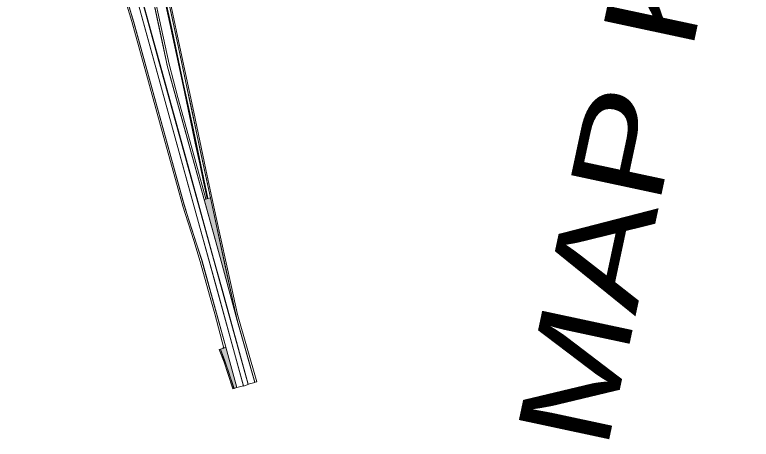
# Model space of a CAD drawing. Extents: x 2363411 to 2369702, y 6977197 to 6988655.
# Drawn here: x 2367822.8 to 2367997.2, y 6986995.7 to 6987096.2 of the extents above; entities that cross this region are included whole.
import ezdxf

# ---------------------------------------------------------------- set-up
doc = ezdxf.new("R2010")
doc.units = 0
doc.header["$LTSCALE"] = 5.6
for name, color, linetype, lineweight in [('10', 7, 'Continuous', 13), ('11', 7, 'Continuous', 13), ('62', 7, 'Continuous', 25)]:
    doc.layers.add(name, color=color, linetype=linetype, lineweight=lineweight)

msp = doc.modelspace()

# ---------------------------------------------------------------- hatches: boundary and pattern name
at = {"layer": '10'}
msp.add_hatch(color=256, dxfattribs=at).paths.add_polyline_path([(2367874.494, 6987007.693), (2367873.305, 6987011.337), (2367872.422, 6987014), (2367871.271, 6987016.959), (2367871.527, 6987017.052), (2367872.505, 6987014.536), (2367873.304, 6987012.164), (2367874.771, 6987007.765)])
at = {"layer": '11'}
for points in [[(2367869.165, 6987052.873), (2367867.69, 6987052.468), (2367871.707, 6987037.882), (2367875.502, 6987023.856)], [(2367872.17, 6987017.298), (2367872.116, 6987017.348), (2367872.266, 6987017.257), (2367872.827, 6987017.511), (2367875.447, 6987007.968), (2367874.753, 6987007.766), (2367873.533, 6987011.524), (2367872.916, 6987013.378), (2367872.311, 6987014.921), (2367871.829, 6987016.311), (2367871.584, 6987017.04)]]:
    msp.add_hatch(color=256, dxfattribs=at).paths.add_polyline_path(points)

# ---------------------------------------------------------------- linework, layer by layer
at = {"layer": '10'}
for points in [[(2367823.847, 6987197.333), (2367823.578, 6987199.272), (2367823.3, 6987201.289), (2367822.847, 6987204.893), (2367826.829, 6987190.573), (2367830.16, 6987178.459), (2367877.023, 6987008.344), (2367875.447, 6987007.968), (2367872.827, 6987017.511), (2367867.099, 6987038.271), (2367862.99, 6987051.158), (2367851.159, 6987094.057), (2367847.606, 6987105.967), (2367844.225, 6987115.816), (2367845.242, 6987116.274), (2367846.105, 6987116.528)], [(2367877.024, 6987008.343), (2367870.839, 6987030.888), (2367864.516, 6987053.601), (2367855.612, 6987086.004), (2367846.758, 6987118.1), (2367840.138, 6987142.135), (2367834.773, 6987161.658), (2367830.143, 6987178.207), (2367831.357, 6987177.911), (2367834.935, 6987165.874), (2367836.63, 6987160.534), (2367842.072, 6987139.896), (2367849.449, 6987112.53), (2367856.739, 6987086.02), (2367878.132, 6987008.714)], [(2367867.682, 6987052.466), (2367863.431, 6987067.933), (2367858.969, 6987084.191), (2367857.989, 6987088.833), (2367854.879, 6987103.19), (2367851.918, 6987116.978), (2367850.808, 6987122.121), (2367848.758, 6987131.552), (2367847.451, 6987136.923), (2367845.67, 6987143.532), (2367843.17, 6987152.957), (2367843.577, 6987153.074), (2367844.964, 6987147.887), (2367846.065, 6987143.795), (2367848.208, 6987135.668), (2367849.111, 6987131.857), (2367850.813, 6987124.2), (2367852.711, 6987115.391), (2367855.664, 6987101.63), (2367857.5, 6987093.19), (2367859.374, 6987084.466), (2367861.492, 6987076.629), (2367864.002, 6987067.529), (2367868.104, 6987052.632)], [(2367852.72, 6987101.019), (2367864.117, 6987059.56), (2367869.942, 6987038.495), (2367871.963, 6987031.24), (2367878.143, 6987008.746), (2367879.699, 6987009.192), (2367875.502, 6987023.856), (2367871.707, 6987037.882), (2367859.359, 6987082.676), (2367858.959, 6987084.27), (2367857.52, 6987090.812), (2367855.222, 6987101.576)], [(2367874.494, 6987007.693), (2367873.305, 6987011.337), (2367872.422, 6987014), (2367871.271, 6987016.959), (2367871.527, 6987017.052), (2367872.505, 6987014.536), (2367873.304, 6987012.164), (2367874.771, 6987007.765)]]:
    msp.add_lwpolyline(points, close=True, dxfattribs=at)
for points in [[(2367847.52, 6987106.153), (2367851.065, 6987094.388), (2367856.259, 6987075.511), (2367860.445, 6987060.353), (2367862.793, 6987051.809), (2367864.102, 6987047.618), (2367865.827, 6987042.245), (2367867.202, 6987037.981), (2367872.785, 6987017.537), (2367872.325, 6987017.297), (2367870.188, 6987025.424), (2367868.941, 6987029.871), (2367866.777, 6987037.824), (2367865.209, 6987042.758), (2367862.621, 6987050.878), (2367861.273, 6987055.784), (2367859.537, 6987062.038), (2367857.326, 6987069.998), (2367854.492, 6987080.29), (2367850.544, 6987094.614), (2367848.103, 6987102.745)], [(2367858.411, 6987100.41), (2367860.008, 6987092.919), (2367861.603, 6987085.362), (2367864.73, 6987070.651), (2367868.541, 6987052.727), (2367868.385, 6987052.681), (2367867.553, 6987056.613), (2367866.631, 6987060.892), (2367865.58, 6987065.796), (2367864.857, 6987069.28), (2367864.209, 6987072.261), (2367862.684, 6987079.435), (2367859.574, 6987094.119), (2367858.098, 6987101.088)], [(2367859.758, 6987098.915), (2367862.194, 6987087.44), (2367865.227, 6987073.157), (2367868.086, 6987059.58), (2367869.536, 6987052.929), (2367870.526, 6987048.241), (2367874.049, 6987032.1), (2367875.557, 6987025.299), (2367880.129, 6987009.324), (2367879.706, 6987009.214), (2367875.555, 6987023.672), (2367874.667, 6987027.693), (2367874.234, 6987029.611), (2367872.535, 6987037.442), (2367869.167, 6987052.891), (2367866.977, 6987063.098), (2367864.08, 6987076.752), (2367862.308, 6987085.139), (2367859.287, 6987099.38)]]:
    msp.add_lwpolyline(points, dxfattribs=at)
at = {"layer": '11'}
msp.add_lwpolyline([(2367859.103, 6987097.195), (2367862.365, 6987081.852), (2367864.899, 6987070.026), (2367868.529, 6987052.767), (2367868.557, 6987052.707), (2367869.165, 6987052.873), (2367866.707, 6987064.466), (2367864.907, 6987072.954), (2367863.36, 6987080.132), (2367861.612, 6987088.434), (2367860.34, 6987094.37), (2367858.437, 6987103.237)], dxfattribs=at)
for points in [[(2367869.165, 6987052.873), (2367867.69, 6987052.468), (2367871.707, 6987037.882), (2367875.502, 6987023.856)], [(2367872.17, 6987017.298), (2367872.116, 6987017.348), (2367872.266, 6987017.257), (2367872.827, 6987017.511), (2367875.447, 6987007.968), (2367874.753, 6987007.766), (2367873.533, 6987011.524), (2367872.916, 6987013.378), (2367872.311, 6987014.921), (2367871.829, 6987016.311), (2367871.584, 6987017.04)]]:
    msp.add_lwpolyline(points, close=True, dxfattribs=at)

# ---------------------------------------------------------------- texts
at = {"layer": '62', "width": 1.35}
msp.add_text('MAP KEY', height=21.87, rotation=77.939, dxfattribs=at).set_placement((2367962.914, 6986992.575))

doc.saveas('drawing.dxf')
